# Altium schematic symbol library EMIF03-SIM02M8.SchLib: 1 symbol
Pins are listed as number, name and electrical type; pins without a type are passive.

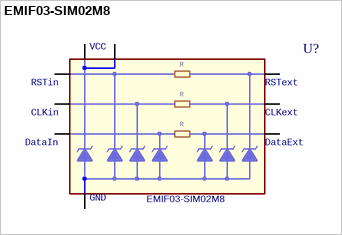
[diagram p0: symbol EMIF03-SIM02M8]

## EMIF03-SIM02M8
designator U?
footprint ST_QFN40P170X150X55-9L
pins: 1 VCC, 2 RSTin, 3 CLKin, 4 DataIn, 5 DataExt, 6 CLKext, 7 RSText, 8 VCC1, 9 GND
